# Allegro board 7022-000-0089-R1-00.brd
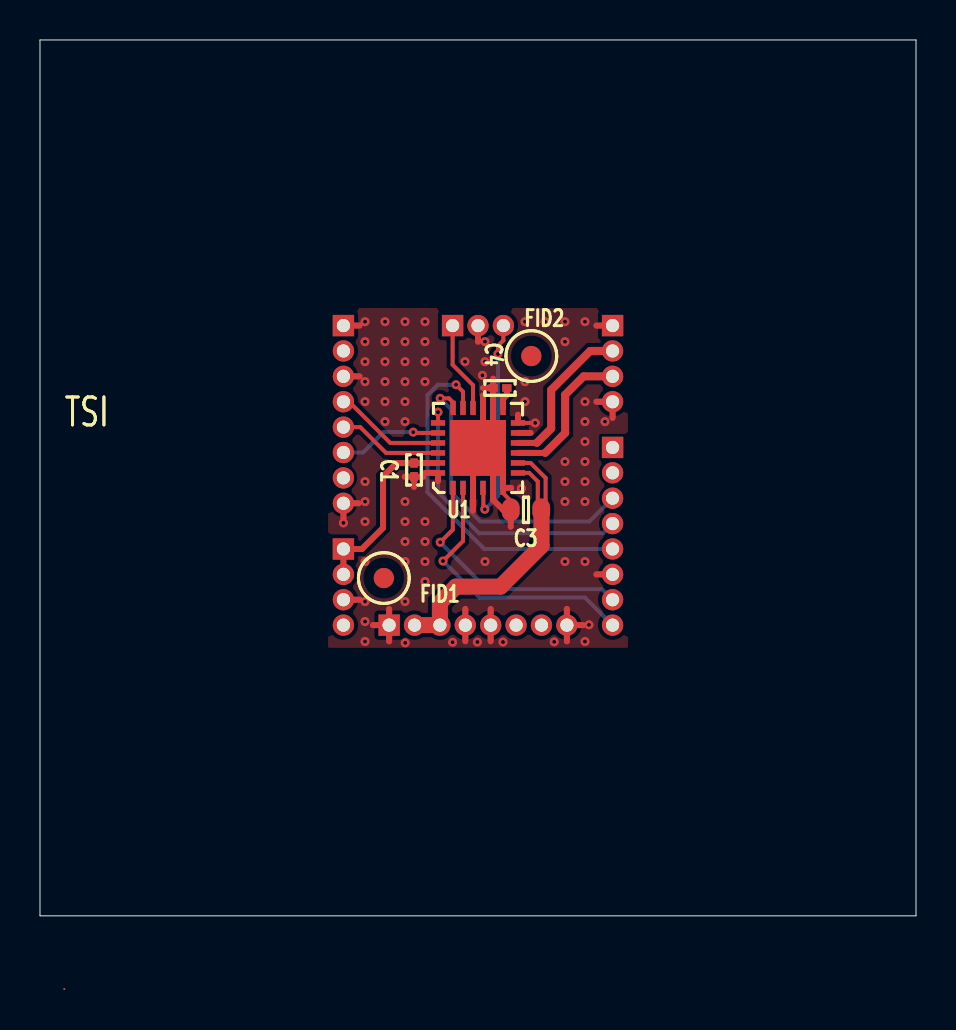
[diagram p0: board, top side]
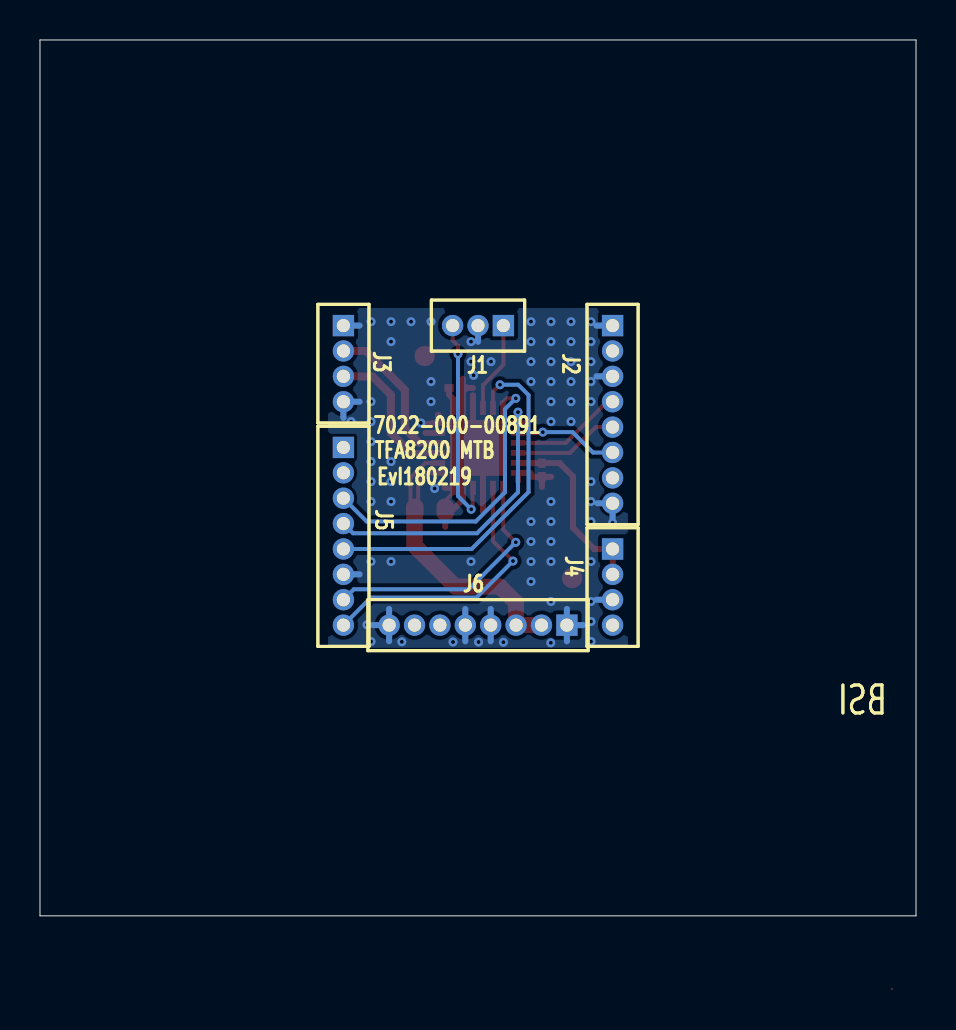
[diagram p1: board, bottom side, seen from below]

Outline 43.81 x 43.81 mm; copper layers: TOP, BOTTOM. Coordinates in mm from the lower left corner of the outline.
Outline path: 0,43.81 0,0 43.81,0 43.81,43.81 0,43.81

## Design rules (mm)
constraint set DEFAULT: 
nets with their own width: nets BCK DATAI FS GND INT SCL SDA
nets with their own width: min track width 0.5; nets VBAT VDDD

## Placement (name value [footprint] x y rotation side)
0001  PCB-NUMBER  [MEC_PCB-NUMBER]  1.22 -3.66 0 top
C1  0.1uF  [CC0201]  18.71 22.31 270 top
C3  22uF  [CC0603_OV]  24.31 20.31 180 top
C4  0.1uF  [CC0201]  23.01 26.41 180 top
FID1  FD 40mil  [FID_40MIL_SM080]  17.2 16.9 0 top
FID2  FD 40mil  [FID_40MIL_SM080]  24.57 28 0 top
J1  HDR_1X3  [CON_1X3_1P27_TH]  20.64 29.53 0 bottom
J2  HDR_1X8  [CON_1X8_1P27_TH]  15.18 29.53 270 bottom
J3  HDR_1X4  [CON_1X4_1P27_TH]  28.64 29.53 270 bottom
J4  HDR_1X4  [CON_1X4_1P27_TH]  15.18 18.35 270 bottom
J5  HDR_1X8  [CON_1X8_1P27_TH]  28.64 23.43 270 bottom
J6  HDR_1X8  [CON_1X8_1P27_TH]  17.46 14.54 0 bottom
NOREF  -  []  29.74 30.41 0 top
NOREF#2  -  []  20.64 29.53 0 top
NOREF#3  -  []  15.18 17.08 90 top
NOREF#4  -  []  35.32 28.21 90 top
NOREF#5  -  []  13.91 30.91 0 top
NOREF#6  -  []  17.46 14.54 0 top
NOREF#7  -  []  23.05 1.77 0 top
NOREF#8  -  []  19.08 24.32 90 top
NOREF#9  -  []  16.58 15.64 0 top
NOREF#10  -  []  -25.09 -113.09 0 top
NOREF#11  -  []  134.91 25.91 0 top
NOREF#12  -  []  29.91 12.91 90 top
NOREF#13  -  []  27.24 13.44 90 top
NOREF#14  -  []  28.64 22.16 90 top
NOREF#15  -  []  5.62 30.41 0 top
NOREF#16  -  []  16.28 19.24 0 top
NOREF#17  -  []  172.91 -81.09 0 top
NOREF#18  -  []  256.91 -122.09 0 top
NOREF#19  -  []  15.18 28.26 90 top
NOREF#20  -  []  172.91 -81.09 0 top
NOREF#21  -  []  256.91 -122.09 0 top
NOREF#22  -  []  24.06 28.43 90 top
NOREF#23  -  []  28.64 28.26 90 top
NOREF#24  -  []  19.75 30.63 0 top
NOREF#25  -  []  21.86 17.04 90 top
NOREF#26  -  []  1.35 24.57 0 top
NOREF#27  -  []  19.08 24.32 0 top
NOREF#28  -  []  5.62 30.41 90 top
NOREF#29  -  []  -114.09 -81.09 180 bottom
NOREF#30  -  []  -114.09 -81.09 180 bottom
U1  TFA8200  [QFN24_0P5_4X4_EP]  21.91 23.41 90 top

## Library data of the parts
0001 = PCB-NUMBER-2
C1 C4 = CAP_NP: Tolerance: TOLERANCE; User Part Number: USERPART#
C3 = CAP_NP
FID1 FID2 = FID-040
J1 = CONN_HDR_3X1
J2 J5 J6 = CONN_HDR_8X1
J3 J4 = CONN_HDR_4X1
U1 = TFA8200_QFN_24P

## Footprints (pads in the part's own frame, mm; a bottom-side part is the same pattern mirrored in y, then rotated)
CC0201
  rect 0.47x0.381 smd: 1(-0.343,0) 2(0.343,0)
CC0603_OV
  oval 0.889x1.143 smd: 1(-0.762,0) 2(0.762,0)
CON_1X3_1P27_TH
  rect 1.067x1.067 hole 0.66: 1(0,0)
  round 1.067 hole 0.66: 2(1.27,0) 3(2.54,0)
CON_1X4_1P27_TH
  rect 1.067x1.067 hole 0.66: 1(0,0)
  round 1.067 hole 0.66: 2(1.27,0) 3(2.54,0) 4(3.81,0)
CON_1X8_1P27_TH
  rect 1.067x1.067 hole 0.66: 1(0,0)
  round 1.067 hole 0.66: 2(1.27,0) 3(2.54,0) 4(3.81,0) 5(5.08,0) 6(6.35,0) 7(7.62,0) 8(8.89,0)
FID_40MIL_SM080
  round 1.016 smd: 1(0,0)
MEC_PCB-NUMBER
  round 0.1 smd: 1(0,0)
QFN24_0P5_4X4_EP
  rect 0.711x0.279 smd: 1(-2,1.25) 2(-2,0.75) 3(-2,0.25) 4(-2,-0.25) 5(-2,-0.75) 6(-2,-1.25) 13(2,-1.25) 14(2,-0.75) 15(2,-0.25) 16(2,0.25) 17(2,0.75) 18(2,1.25)
  rect 0.279x0.711 smd: 7(-1.25,-2) 8(-0.75,-2) 9(-0.25,-2) 10(0.25,-2) 11(0.75,-2) 12(1.25,-2) 19(1.25,2) 20(0.75,2) 21(0.25,2) 22(-0.25,2) 23(-0.75,2) 24(-1.25,2)
  rect 2.794x2.794 smd: 25(0,0)

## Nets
GND: C1.2 C3.2 C4.2 J1.2 J2.1 J2.3 J2.8 J3.1 J3.4 J4.3 J5.6 J6.1 J6.4 J6.5 J6.8 U1.3 U1.5 U1.6 U1.11 U1.12 U1.14 U1.15 U1.24 U1.25
VBAT: C3.1 J6.2 J6.3 U1.7 U1.8(VDDP_2)
VDDD: C1.1 J4.1 J4.2 U1.23
ADS1: J1.1 U1.16
ADS2: J1.3 U1.4
BCK: J2.4 U1.21
BCK2: J5.3 U1.18
DATAI: J2.6 U1.20
DATAI2: J5.5 U1.17
FS: J2.5 U1.22
FS2: J5.4 U1.19
INT: J5.2
OUTN: J3.2 U1.10
OUTP: J3.3 U1.9
SCL: J5.8 U1.2
SDA: J5.7 U1.1
N14931714: C4.1 U1.13

Pads without a net: 0001 1; FID1 1; FID2 1; J2 2 7; J4 4; J5 1; J6 6 7

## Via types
v1: diameter 0.45, hole 0.2, TOP to BOTTOM, 79 vias

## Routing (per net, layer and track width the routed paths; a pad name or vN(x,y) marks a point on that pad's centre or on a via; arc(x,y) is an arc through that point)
GND: length 54.6
  TOP w0.2: 24.89,24.66 v1(24.77,24.66) U1.12 ; 22.66,25.41 U1.14 ; C3.2 23.55,20.76 23.16,21.15 U1.6
  TOP w0.3: 22.66,22.66 U1.25 ; 22.66,22.66 23.16,22.16 U1.6 23.57,21.41 ; 22.66,22.66 U1.5 22.66,20.82 23.17,20.31 C3.2 23.55,19.46 ; U1.25 21.66,23.16 U1.3 21.66,20.26 ; U1.25 22.16,23.66 ; 22.16,26.04 U1.15 22.16,23.66 ; 16.65,14.54 J6.1 ; J6.1 17.46,13.73 ; J6.1 17.46,15.35 ; 27.83,17.08 J5.6 ; 22.16,23.66 22.66,24.16 U1.14 22.66,26.4 C4.2 ; 22.54,15.35 22.54,13.73 ; 21.27,13.73 J6.4 21.27,15.35 ; C4.2 22.66,26.87 ; C4.2 22.15,26.41 ; 26.35,13.73 J6.8 ; J6.8 27.16,14.54 ; J6.8 26.35,15.35 ; 18.71,21.45 C1.2 ; C1.2 19.17,21.96 ; C1.2 18.24,21.96 ; 19.28,22.16 U1.24 19.91,21.74 ; 15.18,19.88 15.18,20.64 15.93,20.64 ; J2.1 15.98,29.53 ; 27.83,29.53 J3.1 ; 28.64,24.91 J3.4 27.83,25.72 ; U1.11 24.54,24.16 ; 21.91,28.72 J1.2 ; U1.12 23.91,25.07 ; J4.3 15.98,15.81 ; J2.3 15.98,26.99
  BOTTOM w0.3: 21.91,28.72 J1.2 ; 27.83,25.72 J3.4 28.64,24.91 ; 15.93,20.64 15.18,20.64 15.18,19.88 ; 22.54,13.73 22.54,15.35 ; J6.1 17.46,15.35 ; J6.1 16.65,14.54 ; J6.1 17.46,13.73 ; 27.83,29.53 J3.1 ; J6.8 27.16,14.54 ; J6.8 26.35,15.35 ; J6.8 26.35,13.73 ; 21.27,13.73 J6.4 21.27,15.35 ; 27.83,17.08 J5.6 ; J2.3 15.98,26.99 ; J4.3 15.98,15.81 ; J2.1 15.98,29.53
  vias: v1(15.18,19.66) v1(16.26,29.72) v1(16.26,28.72) v1(16.26,27.72) v1(16.26,26.72) v1(16.26,25.72) v1(16.26,21.72) v1(16.26,20.72) v1(16.26,19.72) v1(16.26,17.72) v1(16.26,15.72) v1(16.26,14.72) v1(16.26,13.72) v1(17.26,29.72) v1(17.26,28.72) v1(17.26,27.72) v1(17.26,26.72) v1(17.26,25.72) v1(17.26,24.72) v1(18.26,29.72) v1(18.26,28.72) v1(18.26,27.72) v1(18.26,26.72) v1(18.26,25.72) v1(18.26,24.72) v1(18.26,20.72) v1(18.26,19.72) v1(18.26,18.72) v1(18.26,17.72) v1(18.26,15.72) v1(18.27,13.66) v1(19.26,29.72) v1(19.26,28.72) v1(19.26,27.72) v1(19.26,26.72) v1(19.26,19.72) v1(19.26,18.72) v1(19.26,17.72) v1(19.26,16.72) v1(20.64,13.69) v1(21.26,27.72) v1(21.88,13.7) v1(22.13,27.04) v1(22.26,28.72) v1(22.26,27.72) v1(22.26,17.72) v1(23.16,13.7) v1(24.08,21.38) v1(24.26,29.72) v1(24.26,26.72) v1(24.26,25.72) v1(25.26,29.72) v1(25.72,13.71) v1(26.26,29.72) v1(26.26,28.72) v1(26.26,22.72) v1(26.26,21.72) v1(26.26,20.72) v1(26.26,17.72) v1(27.26,29.72) v1(27.26,25.72) v1(27.26,24.72) v1(27.26,23.72) v1(27.26,22.72) v1(27.26,21.72) v1(27.26,20.72) v1(27.26,17.72) v1(27.26,13.72) v1(27.46,14.56) v1(28.26,24.72)
VBAT: length 16.6
  TOP w0.2: U1.8 24.54,22.66 25.29,21.91 25.29,20.53 C3.1 24.9,20.48 24.9,21.73 24.47,22.16 U1.7
  TOP w0.5: C3.1 25.03,20.27
  TOP w0.8: C3.1 25.08,20.29 25.08,18.51 23.04,16.47 20.8,16.47 20,15.67 20,14.54 J6.2
VDDD: length 9.3
  TOP w0.3: U1.23 19.9,22.65 C1.1 17.83,22.65 17.16,21.98 17.16,19.41 16.1,18.35 J4.1 J4.2
ADS1: length 4.5
  TOP w0.2: J1.1 20.64,27.57 21.66,26.55 U1.16
ADS2: length 10.7
  TOP w0.2: J1.3 23.18,28.79 22.91,28.52 v1(22.91,28.11) ; v1(22.25,20.34) 22.18,20.41 22.18,21.31 22.16,21.33 U1.4
  BOTTOM w0.2: v1(22.25,20.34) 22.91,21 v1(22.91,28.11)
BCK: length 5.6
  TOP w0.2: J2.4 15.46,25.72 17.52,23.66 U1.21
BCK2: length 15.1
  TOP w0.2: v1(20.02,25.89) 20.46,25.89 20.66,25.69 U1.18
  BOTTOM w0.2: v1(20.02,25.89) 20.56,25.35 20.56,21.19 22.02,19.73 27.47,19.73 J5.3
DATAI: length 5.2
  TOP w0.2: U1.20 18.71,24.16 v1(18.67,24.2)
  BOTTOM w0.2: v1(18.67,24.2) 17.18,24.2 16.16,23.18 J2.6
DATAI2: length 18.2
  TOP w0.2: U1.17 21.16,26.22 v1(20.81,26.57)
  BOTTOM w0.2: J5.5 22.22,18.35 19.38,21.2 19.38,26.05 19.9,26.57 v1(20.81,26.57)
FS: length 5.3
  TOP w0.2: U1.22 17.31,23.16 16.02,24.45 J2.5
FS2: length 14.3
  TOP w0.2: U1.19 v1(19.91,25.2)
  BOTTOM w0.2: v1(19.91,25.2) 19.91,21.19 21.96,19.14 28.15,19.14 J5.4
OUTN: length 7.8
  TOP w0.3: 24.85,23.66 U1.10
  TOP w0.4: 24.85,23.66 25.57,24.38 25.57,26.31 27.52,28.26 J3.2
OUTP: length 7.4
  TOP w0.3: 25.27,23.16 U1.9
  TOP w0.4: 25.27,23.16 26.27,24.16 26.27,26.07 27.19,26.99 J3.3
SCL: length 13.9
  TOP w0.2: U1.2 21.16,18.75 v1(20.16,17.75)
  BOTTOM w0.2: J5.8 27.26,15.92 21.99,15.92 v1(20.16,17.75)
SDA: length 12.8
  TOP w0.2: v1(20.02,18.69) 20.65,19.32 20.65,21.4 U1.1
  BOTTOM w0.2: J5.7 28.11,16.34 22.37,16.34 v1(20.02,18.69)
N14931714: length 1.1
  TOP w0.3: C4.1 23.35,26.06 23.16,25.87 U1.13

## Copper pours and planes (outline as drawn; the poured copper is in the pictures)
GND on TOP: 14.41,13.41 14.41,30.41 29.41,30.41 29.41,13.41 ; 1 cut-out
GND on BOTTOM: 14.41,13.41 14.41,30.41 29.41,30.41 29.41,13.41 ; 1 cut-out

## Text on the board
Ref Des/Silkscreen Bottom: EvI180219 | TFA8200 MTB | 7022-000-00891
XSECTION_CHART: *  SURFACE - AIR 0 UM | L1 TOP CONDUCTOR - COPPER 18 UM | *  DIELECTRIC - FR-4 1316 UM | L2 BOTTOM CONDUCTOR - COPPER 18 UM | DESIGN CROSS SECTION CHART | ___________________________ | 1-2
User.30: NOTES: | - DRILL SIZES LISTED IN LEGEND | ARE CONSIDERED FINISHED. | - VENDOR IS REQUIRED TO SELECT | TOOLING FOR OVERDRILLING. | - LEGEND DOES NOT SPECIFY DEPTH | INTO ADJACENT DIELECTRIC LAYER. | FIGURE | SIZE | 0.2 | 0.6604 | DRILL CHART: TOP to BOTTOM | ALL UNITS ARE IN MILLIMETERS | TOLERANCE | +0.0/-0.0 | +0.0508/-0.0508 | PLATED | QTY | 79 | 35
